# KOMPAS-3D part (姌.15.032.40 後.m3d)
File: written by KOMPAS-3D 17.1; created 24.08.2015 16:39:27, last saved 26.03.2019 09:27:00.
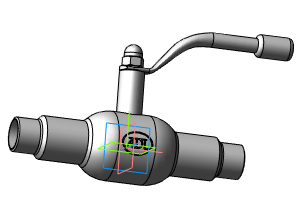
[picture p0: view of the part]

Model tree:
1. Операция без истории:4  (labels: Сталь 20  ГОСТ 1050-88)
